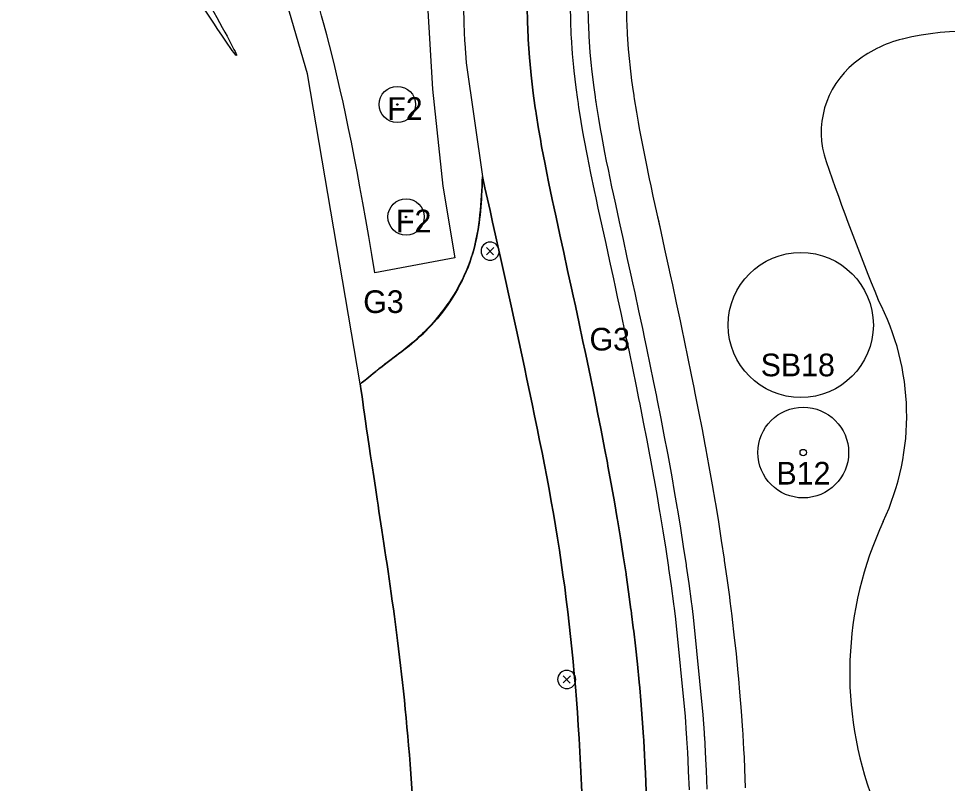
# Model space of a CAD drawing. Extents: x 0 to 512122, y 0 to 6212554.
# Drawn here: x 511709 to 511760.2, y 6211724 to 6211766.1 of the extents above; entities that cross this region are included whole.
import ezdxf

# ---------------------------------------------------------------- set-up
doc = ezdxf.new("R2010")
doc.units = 0
for name, color, linetype in [('_lights', 7, 'Continuous'), ('_ny fruit trees', 7, 'Continuous'), ('_S1_rabarber', 7, 'Continuous'), ('L40 jord udlagt muld og grøft', 7, 'Continuous'), ('MatrikelnummerMaster', 7, 'Continuous'), ('Skel', 7, 'Continuous'), ('TV_U_AFM_Symbl_Gul', 7, 'Continuous'), ('TV_U_LYS_Mastenummer', 7, 'Continuous'), ('TV_U_LYS_Nyx330-Trafiksti-x2', 7, 'Continuous')]:
    doc.layers.add(name, color=color, linetype=linetype)

# ---------------------------------------------------------------- blocks, each defined once
blk = doc.blocks.new('SOLITAIRE TREES')
at = {"layer": 'Skel'}
for radius in [2, 0.141]:
    blk.add_circle((0, 0), radius, dxfattribs=at)

msp = doc.modelspace()

# ---------------------------------------------------------------- linework, layer by layer
at = {"layer": '_lights'}
for p, q in [((511734.824, 6211753.508), (511735.218, 6211753.114)), ((511735.222, 6211753.512), (511734.828, 6211753.118)), ((511739.048, 6211729.898), (511739.442, 6211729.504)), ((511739.446, 6211729.902), (511739.052, 6211729.508))]:
    msp.add_line(p, q, dxfattribs=at)
for centre, start, end in [((511735.021, 6211753.311), 315.5636, 315), ((511735.021, 6211753.311), 315, 315.5636), ((511739.245, 6211729.701), 315.5636, 315), ((511739.245, 6211729.701), 315, 315.5636)]:
    msp.add_arc(centre, 0.5, start, end, dxfattribs=at)
at = {"layer": '_ny fruit trees'}
for centre, radius in [((511729.909, 6211761.402), 1), ((511729.909, 6211761.402), 0.0426), ((511730.392, 6211755.199), 1), ((511730.392, 6211755.199), 0.0426)]:
    msp.add_circle(centre, radius, dxfattribs=at)
at = {"layer": '_S1_rabarber'}
for points in [[(511727.864, 6211745.992), (511727.878, 6211746.003), (511728.186, 6211746.245), (511729.522, 6211747.327), (511732.166, 6211749.256), (511734.408, 6211753.112), (511734.541, 6211756.051), (511734.603, 6211757.422)], [(511734.603, 6211757.422), (511734.541, 6211756.051), (511734.408, 6211753.112), (511732.166, 6211749.256), (511729.522, 6211747.327), (511728.186, 6211746.245), (511727.878, 6211746.003), (511727.864, 6211745.992)], [(511734.603, 6211757.422), (511735.331, 6211754.157), (511736.949, 6211746.893), (511739.141, 6211736.177), (511740.137, 6211725.286), (511740.362, 6211712.579), (511738.054, 6211698.643), (511734.81, 6211686.446), (511733.067, 6211679.907), (511732.568, 6211678.04)], [(511732.568, 6211678.04), (511733.067, 6211679.907), (511734.81, 6211686.446), (511738.054, 6211698.643), (511740.362, 6211712.579), (511740.137, 6211725.286), (511739.141, 6211736.177), (511736.949, 6211746.893), (511735.331, 6211754.157), (511734.603, 6211757.422)], [(511726.316, 6211673.166), (511726.701, 6211673.84), (511729.166, 6211678.46), (511730.77, 6211689.196), (511731.359, 6211707.945), (511730.809, 6211726.91), (511728.592, 6211740.772), (511727.934, 6211745.488), (511727.864, 6211745.992)], [(511727.864, 6211745.992), (511727.934, 6211745.488), (511728.592, 6211740.772), (511730.809, 6211726.91), (511731.359, 6211707.945), (511730.77, 6211689.196), (511729.166, 6211678.46), (511726.701, 6211673.84), (511726.316, 6211673.166)]]:
    msp.add_open_spline(points, degree=3, dxfattribs=at)
at = {"layer": 'L40 jord udlagt muld og grøft'}
for points in [[(511727.864, 6211745.992), (511724.951, 6211763.088), (511722.584, 6211771.227), (511721.08, 6211774.49)], [(511733.565, 6211766.759), (511733.579, 6211765.865), (511733.617, 6211764.906), (511733.624, 6211764.781), (511733.698, 6211763.702), (511734.603, 6211757.422)], [(511737.068, 6211766.772), (511737.08, 6211765.961), (511737.115, 6211765.09), (511737.121, 6211764.976), (511737.189, 6211763.992), (511737.261, 6211763.216), (511737.283, 6211763.009), (511737.4, 6211762.027), (511737.493, 6211761.346), (511737.527, 6211761.114), (511737.537, 6211761.046), (511737.559, 6211760.898), (511737.692, 6211760.067), (511737.793, 6211759.482), (511737.863, 6211759.089), (511738.048, 6211758.112), (511738.145, 6211757.621), (511738.243, 6211757.136), (511738.446, 6211756.161), (511738.531, 6211755.763), (511738.655, 6211755.185), (511738.868, 6211754.209), (511739.082, 6211753.232), (511739.295, 6211752.255), (511739.508, 6211751.278), (511739.601, 6211750.85), (511739.72, 6211750.3), (511739.931, 6211749.321), (511740.14, 6211748.342), (511740.256, 6211747.791), (511740.346, 6211747.363), (511740.384, 6211747.182), (511740.55, 6211746.382), (511740.752, 6211745.401), (511740.888, 6211744.726), (511740.949, 6211744.419), (511741.143, 6211743.436), (511741.333, 6211742.452), (511741.484, 6211741.651), (511741.518, 6211741.466), (511741.698, 6211740.48), (511741.734, 6211740.282), (511741.873, 6211739.493), (511742.032, 6211738.566), (511742.042, 6211738.504), (511742.205, 6211737.514), (511742.361, 6211736.523), (511742.511, 6211735.53), (511742.52, 6211735.468), (511742.653, 6211734.537), (511742.785, 6211733.555), (511742.787, 6211733.541), (511742.815, 6211733.325), (511742.913, 6211732.545), (511742.935, 6211732.358), (511743.03, 6211731.548), (511743.138, 6211730.549), (511743.237, 6211729.549), (511743.266, 6211729.236), (511743.326, 6211728.548), (511743.405, 6211727.546), (511743.474, 6211726.543), (511743.485, 6211726.36), (511743.489, 6211726.308), (511743.533, 6211725.54), (511743.554, 6211725.136), (511743.582, 6211724.536), (511743.62, 6211723.532)], [(511743.62, 6211723.532), (511743.582, 6211724.536), (511743.554, 6211725.136), (511743.533, 6211725.54), (511743.489, 6211726.308), (511743.485, 6211726.36), (511743.474, 6211726.543), (511743.405, 6211727.546), (511743.326, 6211728.548), (511743.266, 6211729.236), (511743.237, 6211729.549), (511743.138, 6211730.549), (511743.03, 6211731.548), (511742.935, 6211732.358), (511742.913, 6211732.545), (511742.815, 6211733.325), (511742.787, 6211733.541), (511742.785, 6211733.555), (511742.653, 6211734.537), (511742.52, 6211735.468), (511742.511, 6211735.53), (511742.361, 6211736.523), (511742.205, 6211737.514), (511742.042, 6211738.504), (511742.032, 6211738.566), (511741.873, 6211739.493), (511741.734, 6211740.282), (511741.698, 6211740.48), (511741.518, 6211741.466), (511741.484, 6211741.651), (511741.333, 6211742.452), (511741.143, 6211743.436), (511740.949, 6211744.419), (511740.888, 6211744.726), (511740.752, 6211745.401), (511740.55, 6211746.382), (511740.384, 6211747.182), (511740.346, 6211747.363), (511740.256, 6211747.791), (511740.14, 6211748.342), (511739.931, 6211749.321), (511739.72, 6211750.3), (511739.601, 6211750.85), (511739.508, 6211751.278), (511739.295, 6211752.255), (511739.082, 6211753.232), (511738.868, 6211754.209), (511738.655, 6211755.185), (511738.531, 6211755.763), (511738.446, 6211756.161), (511738.243, 6211757.136), (511738.145, 6211757.621), (511738.048, 6211758.112), (511737.863, 6211759.089), (511737.793, 6211759.482), (511737.692, 6211760.067), (511737.559, 6211760.898), (511737.537, 6211761.046), (511737.527, 6211761.114), (511737.493, 6211761.346), (511737.4, 6211762.027), (511737.283, 6211763.009), (511737.261, 6211763.216), (511737.189, 6211763.992), (511737.121, 6211764.976), (511737.115, 6211765.09), (511737.08, 6211765.961), (511737.068, 6211766.772)], [(511739.433, 6211766.78), (511739.444, 6211766.025), (511739.476, 6211765.214), (511739.482, 6211765.107), (511739.546, 6211764.187), (511739.614, 6211763.457), (511739.634, 6211763.262), (511739.745, 6211762.331), (511739.834, 6211761.683), (511739.866, 6211761.462), (511739.876, 6211761.396), (511739.897, 6211761.254), (511740.025, 6211760.457), (511740.122, 6211759.893), (511740.19, 6211759.513), (511740.369, 6211758.564), (511740.464, 6211758.085), (511740.56, 6211757.61), (511740.76, 6211756.651), (511740.843, 6211756.258), (511740.967, 6211755.686), (511741.178, 6211754.715), (511741.392, 6211753.738), (511741.606, 6211752.76), (511741.819, 6211751.78), (511741.913, 6211751.351), (511742.032, 6211750.799), (511742.243, 6211749.817), (511742.453, 6211748.833), (511742.57, 6211748.279), (511742.661, 6211747.848), (511742.699, 6211747.666), (511742.866, 6211746.86), (511743.069, 6211745.872), (511743.207, 6211745.191), (511743.268, 6211744.881), (511743.464, 6211743.888), (511743.656, 6211742.894), (511743.809, 6211742.084), (511743.843, 6211741.897), (511744.026, 6211740.899), (511744.062, 6211740.698), (511744.203, 6211739.898), (511744.364, 6211738.958), (511744.374, 6211738.895), (511744.54, 6211737.89), (511744.699, 6211736.883), (511744.85, 6211735.874), (511744.86, 6211735.81), (511744.995, 6211734.862), (511745.13, 6211733.861), (511745.132, 6211733.848), (511745.16, 6211733.627), (511745.235, 6211733.03), (511745.768, 6211727.656), (511745.834, 6211726.694), (511745.846, 6211726.506), (511745.849, 6211726.453), (511745.894, 6211725.667), (511745.916, 6211725.253), (511745.944, 6211724.639), (511745.984, 6211723.612)], [(511739.433, 6211766.78), (511739.444, 6211766.025), (511739.476, 6211765.214), (511739.482, 6211765.107), (511739.546, 6211764.187), (511739.614, 6211763.457), (511739.634, 6211763.262), (511739.745, 6211762.331), (511739.834, 6211761.683), (511739.866, 6211761.462), (511739.876, 6211761.396), (511739.897, 6211761.254), (511740.025, 6211760.457), (511740.122, 6211759.893), (511740.19, 6211759.513), (511740.369, 6211758.564), (511740.464, 6211758.085), (511740.56, 6211757.61), (511740.76, 6211756.651), (511740.843, 6211756.258), (511740.967, 6211755.686), (511741.178, 6211754.715), (511741.392, 6211753.738), (511741.606, 6211752.76), (511741.819, 6211751.78), (511741.913, 6211751.351), (511742.032, 6211750.799), (511742.243, 6211749.817), (511742.453, 6211748.833), (511742.57, 6211748.279), (511742.661, 6211747.848), (511742.699, 6211747.666), (511742.866, 6211746.86), (511743.069, 6211745.872), (511743.207, 6211745.191), (511743.268, 6211744.881), (511743.464, 6211743.888), (511743.656, 6211742.894), (511743.809, 6211742.084), (511743.843, 6211741.897), (511744.026, 6211740.899), (511744.062, 6211740.698), (511744.203, 6211739.898), (511744.364, 6211738.958), (511744.374, 6211738.895), (511744.54, 6211737.89), (511744.699, 6211736.883), (511744.85, 6211735.874), (511744.86, 6211735.81), (511744.995, 6211734.862), (511745.13, 6211733.861), (511745.132, 6211733.848), (511745.16, 6211733.627), (511745.235, 6211733.03), (511745.768, 6211727.656), (511745.834, 6211726.694), (511745.846, 6211726.506), (511745.849, 6211726.453), (511745.894, 6211725.667), (511745.916, 6211725.253), (511745.944, 6211724.639), (511745.984, 6211723.612)], [(511746.983, 6211723.645), (511746.943, 6211724.683), (511746.914, 6211725.303), (511746.893, 6211725.72), (511746.847, 6211726.514), (511746.844, 6211726.568), (511746.832, 6211726.757), (511746.763, 6211727.757), (511746.23, 6211733.131), (511746.152, 6211733.755), (511746.123, 6211733.977), (511746.121, 6211733.991), (511745.985, 6211734.999), (511745.849, 6211735.955), (511745.84, 6211736.019), (511745.687, 6211737.035), (511745.527, 6211738.049), (511745.361, 6211739.061), (511745.35, 6211739.124), (511745.188, 6211740.07), (511745.046, 6211740.874), (511745.01, 6211741.076), (511744.826, 6211742.08), (511744.792, 6211742.268), (511744.638, 6211743.081), (511744.446, 6211744.08), (511744.249, 6211745.076), (511744.187, 6211745.387), (511744.049, 6211746.071), (511743.846, 6211747.063), (511743.678, 6211747.87), (511743.64, 6211748.053), (511743.549, 6211748.485), (511743.431, 6211749.041), (511743.221, 6211750.026), (511743.009, 6211751.01), (511742.89, 6211751.563), (511742.797, 6211751.992), (511742.583, 6211752.973), (511742.369, 6211753.952), (511742.155, 6211754.928), (511741.944, 6211755.898), (511741.821, 6211756.468), (511741.738, 6211756.858), (511741.539, 6211757.811), (511741.444, 6211758.281), (511741.351, 6211758.755), (511741.174, 6211759.692), (511741.107, 6211760.066), (511741.011, 6211760.622), (511740.886, 6211761.405), (511740.865, 6211761.544), (511740.855, 6211761.608), (511740.823, 6211761.826), (511740.736, 6211762.46), (511740.628, 6211763.368), (511740.608, 6211763.559), (511740.543, 6211764.27), (511740.481, 6211765.163), (511740.475, 6211765.266), (511740.444, 6211766.052), (511740.433, 6211766.784)], [(511746.983, 6211723.645), (511746.943, 6211724.683), (511746.914, 6211725.303), (511746.893, 6211725.72), (511746.847, 6211726.514), (511746.844, 6211726.568), (511746.832, 6211726.757), (511746.763, 6211727.757), (511746.23, 6211733.131), (511746.152, 6211733.755), (511746.123, 6211733.977), (511746.121, 6211733.991), (511745.985, 6211734.999), (511745.849, 6211735.955), (511745.84, 6211736.019), (511745.687, 6211737.035), (511745.527, 6211738.049), (511745.361, 6211739.061), (511745.35, 6211739.124), (511745.188, 6211740.07), (511745.046, 6211740.874), (511745.01, 6211741.076), (511744.826, 6211742.08), (511744.792, 6211742.268), (511744.638, 6211743.081), (511744.446, 6211744.08), (511744.249, 6211745.076), (511744.187, 6211745.387), (511744.049, 6211746.071), (511743.846, 6211747.063), (511743.678, 6211747.87), (511743.64, 6211748.053), (511743.549, 6211748.485), (511743.431, 6211749.041), (511743.221, 6211750.026), (511743.009, 6211751.01), (511742.89, 6211751.563), (511742.797, 6211751.992), (511742.583, 6211752.973), (511742.369, 6211753.952), (511742.155, 6211754.928), (511741.944, 6211755.898), (511741.821, 6211756.468), (511741.738, 6211756.858), (511741.539, 6211757.811), (511741.444, 6211758.281), (511741.351, 6211758.755), (511741.174, 6211759.692), (511741.107, 6211760.066), (511741.011, 6211760.622), (511740.886, 6211761.405), (511740.865, 6211761.544), (511740.855, 6211761.608), (511740.823, 6211761.826), (511740.736, 6211762.46), (511740.628, 6211763.368), (511740.608, 6211763.559), (511740.543, 6211764.27), (511740.481, 6211765.163), (511740.475, 6211765.266), (511740.444, 6211766.052), (511740.433, 6211766.784)], [(511742.535, 6211766.791), (511742.545, 6211766.108), (511742.574, 6211765.376), (511742.579, 6211765.28), (511742.637, 6211764.443), (511742.7, 6211763.774), (511742.719, 6211763.593), (511742.821, 6211762.731), (511742.904, 6211762.125), (511742.934, 6211761.917), (511742.944, 6211761.856), (511742.964, 6211761.722), (511743.084, 6211760.969), (511743.177, 6211760.432), (511743.242, 6211760.069), (511743.414, 6211759.157), (511743.505, 6211758.693), (511743.599, 6211758.232), (511743.794, 6211757.294), (511743.877, 6211756.908), (511743.998, 6211756.343), (511744.209, 6211755.378), (511744.244, 6211755.214), (511744.275, 6211755.073), (511744.422, 6211754.401), (511744.637, 6211753.421), (511744.851, 6211752.439), (511744.944, 6211752.008), (511745.064, 6211751.454), (511745.277, 6211750.467), (511745.488, 6211749.477), (511745.606, 6211748.918), (511745.697, 6211748.484), (511745.736, 6211748.3), (511745.904, 6211747.488), (511746.109, 6211746.489), (511746.248, 6211745.801), (511746.311, 6211745.487), (511746.509, 6211744.482), (511746.703, 6211743.474), (511746.858, 6211742.653), (511746.893, 6211742.463), (511747.079, 6211741.448), (511747.115, 6211741.244), (511747.259, 6211740.43), (511747.423, 6211739.473), (511747.434, 6211739.409), (511747.602, 6211738.384), (511747.764, 6211737.356), (511747.92, 6211736.324), (511747.929, 6211736.259), (511748.068, 6211735.289), (511748.206, 6211734.264), (511748.208, 6211734.25), (511748.237, 6211734.023), (511748.339, 6211733.207), (511748.363, 6211733.012), (511748.462, 6211732.162), (511748.576, 6211731.113), (511748.68, 6211730.06), (511748.71, 6211729.73), (511748.774, 6211729.005), (511748.857, 6211727.948), (511748.93, 6211726.891), (511748.942, 6211726.698), (511748.945, 6211726.643), (511748.992, 6211725.833), (511749.014, 6211725.407), (511749.043, 6211724.775), (511749.084, 6211723.716)], [(511742.535, 6211766.791), (511742.545, 6211766.108), (511742.574, 6211765.376), (511742.579, 6211765.28), (511742.637, 6211764.443), (511742.7, 6211763.774), (511742.719, 6211763.593), (511742.821, 6211762.731), (511742.904, 6211762.125), (511742.934, 6211761.917), (511742.944, 6211761.856), (511742.964, 6211761.722), (511743.084, 6211760.969), (511743.177, 6211760.432), (511743.242, 6211760.069), (511743.414, 6211759.157), (511743.505, 6211758.693), (511743.599, 6211758.232), (511743.794, 6211757.294), (511743.877, 6211756.908), (511743.998, 6211756.343), (511744.209, 6211755.378), (511744.422, 6211754.401), (511744.637, 6211753.421), (511744.851, 6211752.439), (511744.944, 6211752.008), (511745.064, 6211751.454), (511745.277, 6211750.467), (511745.488, 6211749.477), (511745.606, 6211748.918), (511745.697, 6211748.484), (511745.736, 6211748.3), (511745.904, 6211747.488), (511746.109, 6211746.489), (511746.248, 6211745.801), (511746.311, 6211745.487), (511746.509, 6211744.482), (511746.703, 6211743.474), (511746.858, 6211742.653), (511746.893, 6211742.463), (511747.079, 6211741.448), (511747.115, 6211741.244), (511747.259, 6211740.43), (511747.423, 6211739.473), (511747.434, 6211739.409), (511747.602, 6211738.384), (511747.764, 6211737.356), (511747.92, 6211736.324), (511747.929, 6211736.259), (511748.068, 6211735.289), (511748.206, 6211734.264), (511748.208, 6211734.25), (511748.237, 6211734.023), (511748.339, 6211733.207), (511748.363, 6211733.012), (511748.462, 6211732.162), (511748.576, 6211731.113), (511748.68, 6211730.06), (511748.71, 6211729.73), (511748.774, 6211729.005), (511748.857, 6211727.948), (511748.93, 6211726.891), (511748.942, 6211726.698), (511748.945, 6211726.643), (511748.992, 6211725.833), (511749.014, 6211725.407), (511749.043, 6211724.775), (511749.084, 6211723.716)]]:
    msp.add_lwpolyline(points, dxfattribs=at)
for points in [[(511734.603, 6211757.422), (511734.541, 6211756.051), (511734.438, 6211753.767), (511733.484, 6211751.658), (511733, 6211750.879)], [(511733, 6211750.879), (511732.652, 6211750.321), (511731.431, 6211748.72), (511729.522, 6211747.327), (511728.186, 6211746.245), (511727.878, 6211746.003), (511727.864, 6211745.992)]]:
    msp.add_open_spline(points, degree=3, dxfattribs=at)
at = {"layer": 'MatrikelnummerMaster'}
msp.add_lwpolyline([(511709.039, 6211784.02), (511731.329, 6211794.65), (511753.839, 6211806.083), (511755.583, 6211803.583), (511754.025, 6211802.931), (511749.976, 6211800.563), (511746.182, 6211797.81), (511742.241, 6211794.091), (511738.319, 6211789.251), (511735.288, 6211783.752), (511733.159, 6211777.92), (511731.942, 6211773.006), (511731.564, 6211766.894), (511731.842, 6211762.252), (511732.411, 6211756.897), (511733.074, 6211752.945), (511728.666, 6211752.117)], dxfattribs=at)
msp.add_open_spline([(511728.666, 6211752.117), (511726.887, 6211763.158), (511723.863, 6211773.002), (511719.725, 6211779.29), (511709.29, 6211782.06), (511728.666, 6211752.117), (511709.29, 6211782.06)], degree=3, dxfattribs=at)
at = {"layer": 'TV_U_LYS_Mastenummer'}
msp.add_circle((511752.141, 6211749.243), 4, dxfattribs=at)
at = {"layer": 'TV_U_LYS_Nyx330-Trafiksti-x2'}
for centre, radius, start, end in [((511759.386, 6211758.381), 6.827, 103.9718, 129.1217), ((511761.251, 6211750.887), 14.549, 38.4983, 103.9718), ((511758.193, 6211759.862), 4.925, 129.2175, 199.0161), ((511887.529, 6211804.437), 141.727, 199.01613, 202.30832), ((511744.162, 6211744.244), 13.817, 335.028, 27.5704), ((511774.615, 6211730.061), 19.777, 155.028, 200.9233)]:
    msp.add_arc(centre, radius, start, end, dxfattribs=at)

# ---------------------------------------------------------------- block references
at = {"layer": 'Skel', "xscale": 1.25, "yscale": 1.25}
msp.add_blockref('SOLITAIRE TREES', (511752.277, 6211742.21), dxfattribs=at)

# ---------------------------------------------------------------- texts
at = {"layer": 'TV_U_AFM_Symbl_Gul'}
for s, p in [('F2', (511729.354, 6211760.553)), ('F2', (511729.837, 6211754.351)), ('G3', (511728.031, 6211749.905)), ('G3', (511740.5, 6211747.836)), ('SB18', (511749.933, 6211746.415)), ('B12', (511750.802, 6211740.446))]:
    msp.add_text(s, height=1.25, dxfattribs=at).set_placement(p)

doc.saveas('drawing.dxf')
